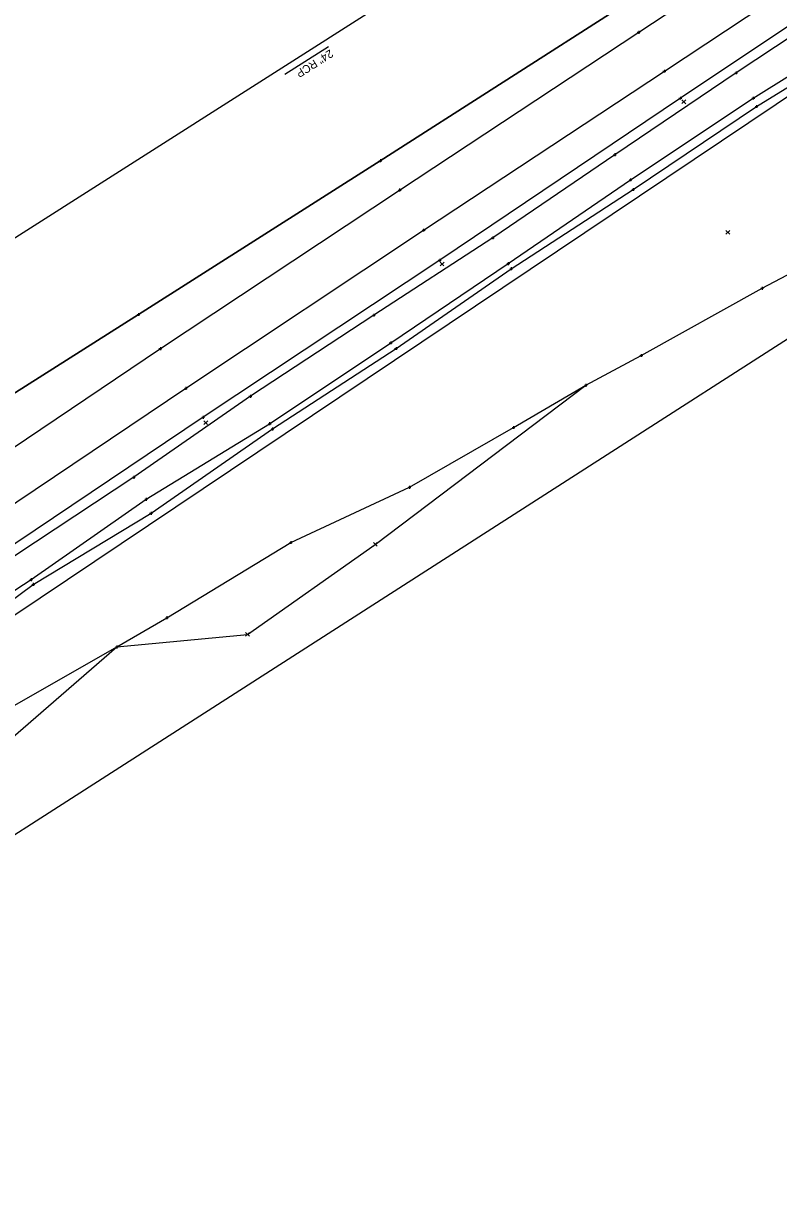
# Model space of a CAD drawing. Extents: x 142461 to 147261, y 511126 to 514697.
# Drawn here: x 145874.4 to 146138.4, y 513430.6 to 513841.1 of the extents above; entities that cross this region are included whole.
import ezdxf

# ---------------------------------------------------------------- set-up
doc = ezdxf.new("R2010")
doc.units = 0
for name, color, linetype in [('DR_X_Ditch', 7, 'Continuous'), ('DR_X_Storm_Sewer', 7, 'Continuous'), ('DR_X_Text', 7, 'Continuous'), ('PM_X_Surveyed_Line', 7, 'Continuous'), ('PV_X_EOP', 7, 'Continuous'), ('RD_X_Fence', 7, 'Continuous'), ('SV_X_Original_Ground', 7, 'Continuous'), ('SV_X_Random_Point', 7, 'Continuous'), ('SV_X_Shot_Marker', 7, 'Continuous'), ('SV_X_Toe_of_Slope', 7, 'Continuous'), ('SV_X_Top_of_Bank', 7, 'Continuous'), ('VG_X_Tree_Line_Rt', 7, 'Continuous')]:
    doc.layers.add(name, color=color, linetype=linetype)

msp = doc.modelspace()

# ---------------------------------------------------------------- linework, layer by layer
at = {"layer": 'DR_X_Ditch'}
msp.add_lwpolyline([(145386.4, 513252.89), (145408.78, 513256.49), (145429.54, 513276.94), (145489.16, 513340.03), (145533.69, 513381.77), (145576.95, 513417.23), (145602.5, 513436.64), (145618.53, 513452.63), (145659.11, 513482.53), (145699, 513517.7), (145727.05, 513538.62), (145763.48, 513565.99), (145800.67, 513596.26), (145837.36, 513620.59), (145877.05, 513646.45), (145917.26, 513674.58), (145960.44, 513701.03), (146002.8, 513729.3), (146043.92, 513757.04), (146086.65, 513786.36), (146129.61, 513814.93), (146171.44, 513841.06), (146212.88, 513868.99), (146235.35, 513884.08)], dxfattribs=at)
at = {"layer": 'DR_X_Storm_Sewer'}
msp.add_line((146183.01, 513964.68), (145764.65, 513697.97), dxfattribs=at)
at = {"layer": 'DR_X_Text'}
msp.add_line((145965.82, 513823.37), (145981.04, 513833.08), dxfattribs=at)
at = {"layer": 'PM_X_Surveyed_Line'}
for points in [[(145307.75, 513247.77), (145337.8, 513273.35), (145402.01, 513328.15), (145492.27, 513403.98), (145551.47, 513453.67), (145589.5, 513485), (145652.45, 513535.43), (145708.49, 513578.45), (145823.05, 513660.55), (145922.26, 513727.29), (146005.91, 513782.8), (146089.52, 513838.01), (146168.07, 513889.83), (146245.86, 513941.57), (146299.38, 513977.14)], [(145071.95, 513203.81), (145158.73, 513259.05), (145217.02, 513295.98), (145277.61, 513334.31), (145360.24, 513386.81), (145456.59, 513448.28), (145523.93, 513491.08), (145564.47, 513516.91), (145634.3, 513561.26), (145696.38, 513600.68), (145817.65, 513677.73), (145914.61, 513739.23), (145999.16, 513793.04), (146085.16, 513848.04), (146162.9, 513897.7)], [(145321.53, 513222.56), (145353.45, 513259.97), (145411.74, 513315.95), (145502.86, 513392.29), (145560.91, 513440.87), (145599.98, 513473.12), (145662.14, 513522.91), (145718.75, 513566.31), (145832.41, 513647.03), (145931.14, 513713.4), (146014.31, 513768.75), (146098.5, 513824.38), (146177.34, 513876.68)]]:
    msp.add_lwpolyline(points, dxfattribs=at)
at = {"layer": 'PV_X_EOP'}
for p, q in [((146183.28, 513867.86), (146104.09, 513814.94)), ((146104.09, 513814.94), (146019.94, 513758.21)), ((146019.94, 513758.21), (145937.21, 513703.28)), ((145937.21, 513703.28), (145838.65, 513637.01))]:
    msp.add_line(p, q, dxfattribs=at)
at = {"layer": 'RD_X_Fence'}
msp.add_lwpolyline([(143478.94, 512019.34), (143711.38, 512177.16), (144427.62, 512645.69), (144477.47, 512681.98), (144582.58, 512758.57), (144706.18, 512806.24), (144763.41, 512828.73), (144839.36, 512854.89), (144928.89, 512885.13), (144926.13, 512699.9), (144921.71, 512476.45), (144997.12, 512524.34), (145097.9, 512588.02), (145394.3, 512776.52), (145562.04, 512882.95), (145736.06, 512993.23), (145625.27, 513165.45), (145520.47, 513331.41), (145754.83, 513482.5), (146985.53, 514272.72), (147146.04, 514395.19)], dxfattribs=at)
at = {"layer": 'SV_X_Original_Ground'}
for points in [[(146162.9, 513897.7), (146085.16, 513848.04), (145999.16, 513793.04), (145914.61, 513739.23), (145817.65, 513677.73), (145696.38, 513600.68), (145634.3, 513561.26), (145564.47, 513516.91), (145523.93, 513491.08), (145456.59, 513448.28), (145360.24, 513386.81), (145277.61, 513334.31), (145217.02, 513295.98), (145158.73, 513259.05), (145071.95, 513203.81)], [(145625.27, 513165.45), (145576.14, 513231.29), (145543.81, 513280.26), (145520.47, 513331.41), (145548.97, 513359.35), (145590.11, 513381.65), (145606.87, 513393.06), (145641.81, 513412.6), (145687.04, 513442.28), (145738.27, 513472.34), (145754.83, 513482.5), (145782.33, 513501.41), (145845.81, 513569.83), (145907.04, 513622.91), (145952.73, 513627.29), (145997.4, 513658.8), (146071.03, 513714.47), (146090.42, 513724.89), (146132.72, 513748.42), (146182.21, 513774.53)]]:
    msp.add_lwpolyline(points, dxfattribs=at)
at = {"layer": 'SV_X_Random_Point'}
for p, q in [((146104.63, 513813.02), (146105.98, 513814.35)), ((146104.64, 513814.36), (146105.96, 513813.01)), ((146120.05, 513767.33), (146121.39, 513768.67)), ((146120.05, 513768.67), (146121.39, 513767.33)), ((146020.09, 513756.26), (146021.44, 513757.58)), ((146020.11, 513757.59), (146021.42, 513756.25)), ((145937.45, 513700.73), (145938.8, 513702.05)), ((145937.46, 513702.06), (145938.78, 513700.71)), ((145996.73, 513658.13), (145998.06, 513659.47)), ((145996.73, 513659.47), (145998.06, 513658.13)), ((145952.06, 513626.63), (145953.4, 513627.96)), ((145952.06, 513627.96), (145953.4, 513626.63))]:
    msp.add_line(p, q, dxfattribs=at)
at = {"layer": 'SV_X_Shot_Marker'}
for p, q in [((146089.02, 513838.01), (146090.02, 513838)), ((146089.53, 513838.51), (146089.52, 513837.51)), ((146089.52, 513838.01), (146089.52, 513838.01)), ((146098, 513824.38), (146099, 513824.37)), ((146098.51, 513824.88), (146098.49, 513823.88)), ((146098.5, 513824.38), (146098.5, 513824.38)), ((146123.6, 513824.3), (146123.6, 513823.3)), ((146123.1, 513823.8), (146124.1, 513823.8)), ((146123.6, 513823.8), (146123.6, 513823.8)), ((146103.59, 513814.94), (146104.59, 513814.93)), ((146104.09, 513815.44), (146104.08, 513814.44)), ((146104.09, 513814.94), (146104.09, 513814.94)), ((146129.11, 513814.93), (146130.11, 513814.93)), ((146129.61, 513815.43), (146129.61, 513814.43)), ((146129.61, 513814.93), (146129.61, 513814.93)), ((146130.2, 513812.04), (146131.2, 513812.04)), ((146130.7, 513812.54), (146130.7, 513811.54)), ((146130.7, 513812.04), (146130.7, 513812.04)), ((146081.12, 513795.64), (146081.12, 513794.64)), ((145998.66, 513793.05), (145999.66, 513793.04)), ((145999.17, 513793.54), (145999.16, 513792.54)), ((145999.16, 513793.04), (145999.16, 513793.04)), ((146080.62, 513795.14), (146081.62, 513795.14)), ((146081.12, 513795.14), (146081.12, 513795.14)), ((146005.91, 513783.3), (146005.9, 513782.3)), ((146086.15, 513786.36), (146087.15, 513786.36)), ((146086.65, 513786.86), (146086.65, 513785.86)), ((146086.65, 513786.36), (146086.65, 513786.36)), ((146087.08, 513783), (146088.08, 513783)), ((146087.58, 513783.5), (146087.58, 513782.5)), ((146087.58, 513783), (146087.58, 513783)), ((146005.41, 513782.8), (146006.41, 513782.79)), ((146005.91, 513782.8), (146005.91, 513782.8)), ((146013.81, 513768.75), (146014.81, 513768.74)), ((146014.32, 513769.25), (146014.3, 513768.25)), ((146014.31, 513768.75), (146014.31, 513768.75)), ((146038.48, 513766.56), (146038.48, 513765.56)), ((146037.98, 513766.06), (146038.98, 513766.06)), ((146038.48, 513766.06), (146038.48, 513766.06)), ((146019.94, 513758.71), (146019.93, 513757.71)), ((146019.44, 513758.22), (146020.44, 513758.21)), ((146019.94, 513758.21), (146019.94, 513758.21)), ((146043.42, 513757.04), (146044.42, 513757.04)), ((146043.92, 513757.54), (146043.92, 513756.54)), ((146043.92, 513757.04), (146043.92, 513757.04)), ((146044.42, 513755.26), (146045.42, 513755.26)), ((146044.92, 513755.76), (146044.92, 513754.76)), ((146044.92, 513755.26), (146044.92, 513755.26)), ((146132.22, 513748.42), (146133.22, 513748.42)), ((146132.72, 513748.92), (146132.72, 513747.92)), ((146132.72, 513748.42), (146132.72, 513748.42)), ((145914.11, 513739.23), (145915.11, 513739.22)), ((145914.62, 513739.73), (145914.61, 513738.73)), ((145914.61, 513739.23), (145914.61, 513739.23)), ((145996.41, 513739.02), (145997.41, 513739.02)), ((145996.91, 513739.52), (145996.91, 513738.52)), ((145996.91, 513739.02), (145996.91, 513739.02)), ((146002.8, 513729.8), (146002.8, 513728.8)), ((145921.76, 513727.3), (145922.76, 513727.29)), ((145922.27, 513727.79), (145922.26, 513726.79)), ((145922.26, 513727.29), (145922.26, 513727.29)), ((146002.3, 513729.3), (146003.3, 513729.3)), ((146002.8, 513729.3), (146002.8, 513729.3)), ((146004.15, 513727.32), (146005.15, 513727.32)), ((146004.65, 513727.82), (146004.65, 513726.82)), ((146004.65, 513727.32), (146004.65, 513727.32)), ((146089.92, 513724.89), (146090.92, 513724.89)), ((146090.42, 513725.39), (146090.42, 513724.39)), ((146090.42, 513724.89), (146090.42, 513724.89)), ((145930.64, 513713.4), (145931.64, 513713.39)), ((145931.15, 513713.9), (145931.13, 513712.9)), ((145931.14, 513713.4), (145931.14, 513713.4)), ((146070.53, 513714.47), (146071.53, 513714.47)), ((146071.03, 513714.97), (146071.03, 513713.97)), ((146071.03, 513714.47), (146071.03, 513714.47)), ((145953.22, 513710.61), (145954.22, 513710.61)), ((145953.72, 513711.11), (145953.72, 513710.11)), ((145953.72, 513710.61), (145953.72, 513710.61)), ((145936.71, 513703.28), (145937.71, 513703.27)), ((145937.22, 513703.78), (145937.21, 513702.78)), ((145937.21, 513703.28), (145937.21, 513703.28)), ((145959.94, 513701.03), (145960.94, 513701.03)), ((145960.44, 513701.53), (145960.44, 513700.53)), ((145960.44, 513701.03), (145960.44, 513701.03)), ((145960.97, 513699.18), (145961.97, 513699.18)), ((145961.47, 513699.68), (145961.47, 513698.68)), ((145961.47, 513699.18), (145961.47, 513699.18)), ((146045.25, 513699.69), (146046.25, 513699.69)), ((146045.75, 513700.19), (146045.75, 513699.19)), ((146045.75, 513699.69), (146045.75, 513699.69)), ((145912.46, 513682.26), (145913.46, 513682.26)), ((145912.96, 513682.76), (145912.96, 513681.76)), ((145912.96, 513682.26), (145912.96, 513682.26)), ((146008.86, 513678.77), (146009.86, 513678.77)), ((146009.36, 513679.27), (146009.36, 513678.27)), ((146009.36, 513678.77), (146009.36, 513678.77)), ((145916.76, 513674.58), (145917.76, 513674.58)), ((145917.26, 513675.08), (145917.26, 513674.08)), ((145917.26, 513674.58), (145917.26, 513674.58)), ((145918.49, 513669.66), (145919.49, 513669.66)), ((145918.99, 513670.16), (145918.99, 513669.16)), ((145918.99, 513669.66), (145918.99, 513669.66)), ((145967.89, 513659.96), (145967.89, 513658.96)), ((145967.39, 513659.46), (145968.39, 513659.46)), ((145967.89, 513659.46), (145967.89, 513659.46)), ((145876.55, 513646.45), (145877.55, 513646.45)), ((145877.05, 513646.95), (145877.05, 513645.95)), ((145877.05, 513646.45), (145877.05, 513646.45)), ((145877.29, 513644.78), (145878.29, 513644.78)), ((145877.79, 513645.28), (145877.79, 513644.28)), ((145877.79, 513644.78), (145877.79, 513644.78)), ((145924.02, 513633.11), (145925.02, 513633.11)), ((145924.52, 513633.61), (145924.52, 513632.61)), ((145924.52, 513633.11), (145924.52, 513633.11)), ((145906.54, 513622.91), (145907.54, 513622.91)), ((145907.04, 513623.41), (145907.04, 513622.41)), ((145907.04, 513622.91), (145907.04, 513622.91))]:
    msp.add_line(p, q, dxfattribs=at)
at = {"layer": 'SV_X_Toe_of_Slope'}
msp.add_lwpolyline([(145729.63, 513535.45), (145766.26, 513563.52), (145800.81, 513589.5), (145840.35, 513616.94), (145877.79, 513644.78), (145918.99, 513669.66), (145961.47, 513699.18), (146004.65, 513727.32), (146044.92, 513755.26), (146087.58, 513783), (146130.7, 513812.04), (146173.86, 513838.64)], dxfattribs=at)
at = {"layer": 'SV_X_Top_of_Bank'}
for points in [[(146165.18, 513851.43), (146123.6, 513823.8), (146081.12, 513795.14), (146038.48, 513766.06), (145996.91, 513739.02), (145953.72, 513710.61), (145912.96, 513682.26), (145871.69, 513654.96), (145844.72, 513636.6), (145803.64, 513608.1), (145763.28, 513578.95), (145723.11, 513548.85), (145651.86, 513491.09), (145611.54, 513461.37), (145571.27, 513430.64)], [(145590.68, 513407.46), (145625.19, 513438.35), (145673.47, 513467.57), (145721.45, 513496.43), (145736.44, 513510), (145754.09, 513524.42), (145769.05, 513536.07), (145812.7, 513565.17), (145852.51, 513591.82), (145907.04, 513622.91), (145924.52, 513633.11), (145967.89, 513659.46), (146009.36, 513678.77), (146045.75, 513699.69), (146071.03, 513714.47), (146090.42, 513724.89), (146132.72, 513748.42), (146182.21, 513774.53)]]:
    msp.add_lwpolyline(points, dxfattribs=at)
at = {"layer": 'VG_X_Tree_Line_Rt'}
msp.add_lwpolyline([(146947.66, 514356.52), (145717.97, 513531.12), (145371.07, 513226.4), (145377.36, 513214.09), (145451.54, 513178.28), (145503.58, 513133.27), (145545.91, 513109.97), (145608.82, 513056.73), (145605.74, 513033.91), (145581.95, 513002.11), (145555.75, 512960.91), (145522.34, 512932.07), (145469.09, 512903.96), (145424.74, 512872.58), (145381.48, 512852.38), (145321.04, 512823.39), (145281.26, 512801.98), (145242.36, 512776.09), (145202.57, 512754.4), (145176.31, 512745.17), (145105.34, 512757.26), (145049.76, 512717.92), (145016.26, 512713.4), (144997.12, 512524.34)], dxfattribs=at)

# ---------------------------------------------------------------- texts
at = {"layer": 'DR_X_Text'}
msp.add_text('24" RCP', height=2.8, rotation=212.5178, dxfattribs=at).set_placement((145981.54, 513832.09))

doc.saveas('drawing.dxf')
